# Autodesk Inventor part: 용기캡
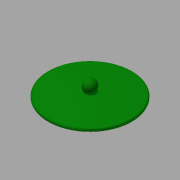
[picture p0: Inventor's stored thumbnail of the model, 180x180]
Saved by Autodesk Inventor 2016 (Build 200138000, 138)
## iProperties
Created: 2018-01
Part Number: 용기캡
Material: ABS 플라스틱
Document SubType Name: Modeling
Designer: mduedu
Density: 1 g/cm^3
Appearance: 진녹색
Author: mduedu
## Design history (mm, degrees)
sketch "스케치1"
  geometry: L1 (-35, 2.5)-(0, 2.5); L2 (0, 5)-(0, 0); L3 (0, 0)-(-35, 0); L4 (-35, 0)-(-35, 2.5); L5 (-31, 0)-(-29, 0); L6 (-29, 0)-(-29, -2); L7 (-29, -2)-(-31, -2); L8 (-31, -2)-(-31, 0); A1 r 246.25 centre (0, -241.25) between (0, 5) and (-35, 2.5); 1 further point
  constraints: 16 end point, 4 parallel, 2 horizontal, 2 perpendicular, 2 point on circle, 1 centre point, 1 coincident, 1 midpoint, 1 point on line, 1 vertical alignment
  dimensions: "d2" = 70 diameter of L4 L2; "d3" = 5 distance from line of L2.start L3; "d4" = 2.5 distance of L3.end L1.start; "d5" = 4 distance between parallel lines of L8 L4; "d6" = 2 distance of L6.end L7.end; "d7" = 2 distance between parallel lines of L7 L3
revolve "회전1" sketch "스케치1" stored, may be unused: angle "d8" = 90 deg
chamfer "모따기1" distance "d9" = 0.5; stored, may be unused: second distance "d10" = 2, angle "d11" = 45 deg
fillet "모깎기1" dims "d12" = 1
fillet "모깎기2" dims "d13" = 1
sketch "스케치2"
  geometry: L1 (-30.5, -2)-(-31, -1.5) reference; L2 (-31, -1.5)-(-31, 0) reference; L3 (-31, 0)-(-34, 0) reference; L4 (-35, 1)-(-35, 1.632) reference; L5 (35, 1.632)-(35, 1) reference; L6 (34, 0)-(31, 0) reference; L7 (31, 0)-(31, -1.5) reference; L8 (31, -1.5)-(30.5, -2) reference; L9 (30.5, -2)-(29, -2) reference; L10 (29, -2)-(29, -1) reference; L11 (28, 0)-(-28, 0) reference; L12 (-29, -1)-(-29, -2) reference; L13 (-29, -2)-(-30.5, -2) reference; L14 (0, 14)-(0, 4); A1 r 1 centre (-34, 1) between (-35, 1) and (-34, 0) reference; A2 r 1 centre (-34, 1.632) between (-34.139, 2.622) and (-35, 1.632) reference; A3 r 246.25 centre (0, -241.25) between (34.139, 2.622) and (-34.139, 2.622) reference; A4 r 1 centre (34, 1.632) between (35, 1.632) and (34.139, 2.622) reference; A5 r 1 centre (34, 1) between (34, 0) and (35, 1) reference; A6 r 1 centre (28, -1) between (29, -1) and (28, 0) reference; A7 r 1 centre (-28, -1) between (-28, 0) and (-29, -1) reference; A8 r 5 centre (0, 9) between (0, 14) and (0, 4); 3 further points
  constraints: 2 end point, 2 midpoint, 2 point on circle, 1 centre point, 1 coincident, 1 perpendicular, 1 point on line, 1 vertical alignment
  dimensions: "d14" = 10 diameter of A8; "d16" = 9 distance of A8.centre point (0, 0)
revolve "회전2" sketch "스케치2" stored, may be unused: angle "d17" = 90 deg
fillet "모깎기3" dims "d18" = 1
node "솔리드1"
node "절단 모서리 투영1"
